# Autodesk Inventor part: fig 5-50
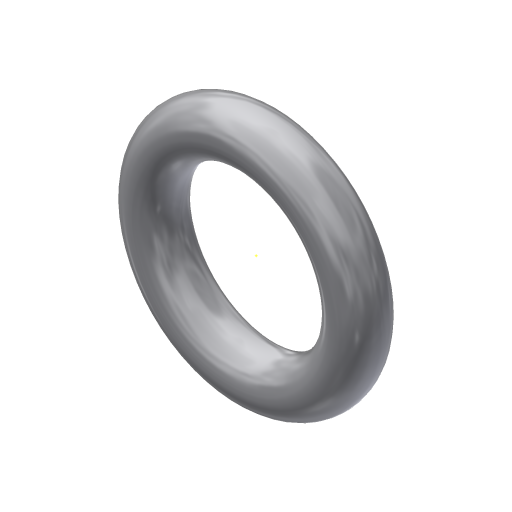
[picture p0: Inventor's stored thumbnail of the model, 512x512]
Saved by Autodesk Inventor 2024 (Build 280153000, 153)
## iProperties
Created: 2010-02
Part Number: fig 5-50
Document SubType Name: Modeling
Designer: CADSoft
Density: 1 g/cm^3
Material: Generic
Appearance: Default
Author: CADSoft
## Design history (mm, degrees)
sketch "Sketch1"
  geometry: L1 (0, 21.37)-(0, -16.247); C1 r 5 at (20.026, 0); 1 further point
  constraints: 2 end point, 1 centre point
  dimensions: "d0" = 10 diameter of C1
revolve "Revolution1" sketch "Sketch1" stored, may be unused: angle "d1" = 90 deg
workpoint "Work Point1"
body "Solid1"
